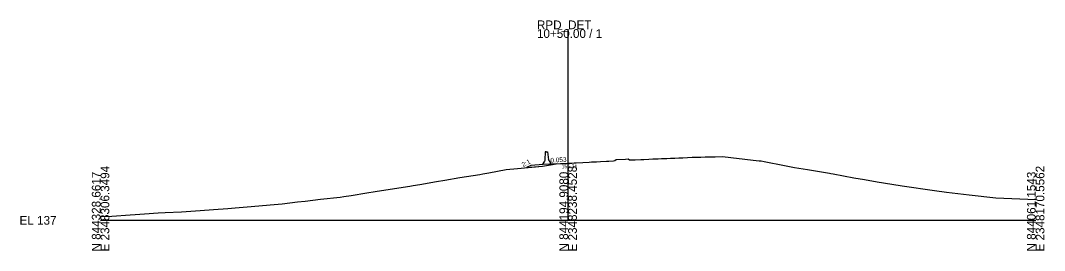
# Model space of a CAD drawing. Extents: x -26 to 2348503, y -10 to 844218.
# Drawn here: x -25.7 to 302.8, y 490.3 to 564.1 of the extents above; entities that cross this region are included whole.
import ezdxf

# ---------------------------------------------------------------- set-up
doc = ezdxf.new("R2010")
doc.units = 0
for name, color, linetype in [('Default', 7, 'Continuous'), ('Exist Cross Section Cell', 7, 'Continuous'), ('Exist XS Center Line Elevation Label', 7, 'Continuous'), ('Exist XS Ground Line', 7, 'Continuous'), ('Old_Level_1', 7, 'Continuous'), ('Prop CMT Pvmt Surface', 7, 'Continuous'), ('Prop CMT Slope Grass', 7, 'Continuous'), ('Prop XS Earthwork Shape', 7, 'Continuous'), ('Prop XS SE Text', 7, 'Continuous'), ('Typical Median Barrier CELL', 7, 'Continuous')]:
    doc.layers.add(name, color=color, linetype=linetype)

# ---------------------------------------------------------------- blocks, each defined once
blk = doc.blocks.new('TYPE T DOUBLE FACE BARRIER')
at = {"layer": 'Typical Median Barrier CELL'}
for p, q in [((-0.33, 3.83), (-0.6, 1.3)), ((0, 3.83), (-0.33, 3.83)), ((0, 3.83), (0.33, 3.83)), ((0.33, 3.83), (0.6, 1.3)), ((-0.75, 0.91), (-1.21, 0.25)), ((-1.21, -0.17), (-1.21, 0.25)), ((0, 0), (0, 0)), ((0.75, 0.91), (1.21, 0.25)), ((1.21, -0.17), (1.21, 0.25)), ((-1.21, -0.17), (1.21, -0.17))]:
    blk.add_line(p, q, dxfattribs=at)
for centre, start, end in [((-1.43, 1.38), 325.0039, 353.9447), ((1.43, 1.38), 186.0553, 214.9937)]:
    blk.add_arc(centre, 0.833, start, end, dxfattribs=at)

msp = doc.modelspace()

# ---------------------------------------------------------------- linework, layer by layer
at = {"layer": 'Exist Cross Section Cell'}
for p, q in [((150, 500), (150, 561.34)), ((0, 500), (150, 500)), ((150, 500), (300, 500))]:
    msp.add_line(p, q, dxfattribs=at)
at = {"layer": 'Exist XS Ground Line'}
msp.add_lwpolyline([(0, 501.22), (3.64, 501.37), (9.54, 501.81), (11.08, 501.89), (14.11, 502.12), (18.52, 502.39), (20.76, 502.52), (25.96, 502.71), (31.97, 503.18), (36.2, 503.5), (40.83, 503.82), (43.19, 504.01), (48.27, 504.43), (54.4, 504.92), (55.71, 505.05), (58.29, 505.32), (63.15, 505.94), (65.62, 506.19), (70.59, 506.77), (76.83, 507.48), (78.03, 507.6), (80.38, 507.97), (85.47, 508.79), (88.05, 509.24), (92.91, 510.03), (99.26, 510.97), (100.34, 511.15), (102.48, 511.52), (107.78, 512.44), (110.48, 512.9), (115.22, 513.7), (121.69, 514.76), (122.66, 514.94), (124.57, 515.26), (130.1, 516.26), (133.75, 516.63), (141.73, 517.43), (145.03, 517.97), (146.18, 518.12), (147.57, 518.2), (148.2, 518.23), (149.2, 518.27), (150, 518.31), (151.24, 518.37), (151.94, 518.41), (152.61, 518.45), (154.71, 518.57), (156.79, 518.69), (157.52, 518.73), (159.12, 518.81), (160.34, 518.87), (162.27, 518.98), (163.08, 519.03), (164.51, 519.11), (165.02, 519.16), (165.4, 519.55), (168.44, 519.65), (169.3, 519.69), (169.7, 519.38), (170.14, 519.39), (170.5, 519.4), (171.56, 519.44), (173.31, 519.52), (173.97, 519.55), (174.31, 519.57), (175.85, 519.65), (177.15, 519.71), (177.74, 519.74), (178.86, 519.78), (179.97, 519.82), (181.1, 519.86), (181.68, 519.88), (182.9, 519.92), (184.27, 519.98), (185.52, 520.04), (186.84, 520.09), (188.33, 520.16), (189.82, 520.22), (190.68, 520.25), (191.1, 520.27), (192.53, 520.32), (193.92, 520.38), (194.41, 520.4), (195.03, 520.41), (196.05, 520.41), (197.15, 520.42), (199.49, 520.45), (209.39, 519.33), (211.24, 519.13), (211.93, 519.05), (212.94, 518.85), (219.37, 517.59), (222.63, 517), (226.8, 516.29), (233.84, 515.11), (234.24, 515.04), (235.04, 514.9), (241.68, 513.68), (245.06, 513.08), (249.12, 512.36), (256.56, 511.17), (257.13, 511.08), (267.49, 509.54), (271.44, 509.06), (278.65, 508.15), (287.23, 507.18), (300, 506.71)], dxfattribs=at)
at = {"layer": 'Prop CMT Pvmt Surface'}
msp.add_line((146.18, 518.12), (142, 517.9), dxfattribs=at)
at = {"layer": 'Prop CMT Slope Grass'}
for p, q in [((138, 517.58), (136.69, 516.92)), ((142, 517.9), (138, 517.58))]:
    msp.add_line(p, q, dxfattribs=at)
at = {"layer": 'Prop XS Earthwork Shape'}
msp.add_lwpolyline([(146.18, 518.12), (142, 517.9), (138, 517.58), (136.69, 516.92), (141.73, 517.43), (145.03, 517.97)], close=True, dxfattribs=at)

# ---------------------------------------------------------------- block references
at = {"layer": 'Old_Level_1', "yscale": -0.9999999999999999, "rotation": -177.10656027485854}
msp.add_blockref('TYPE T DOUBLE FACE BARRIER', (143.2, 518.13), dxfattribs=at)

# ---------------------------------------------------------------- texts
at = {"layer": 'Default'}
msp.add_text('-', height=0.0001, dxfattribs=at).set_placement((0, 500))
at = {"layer": 'Exist Cross Section Cell'}
for s, p in [('RPD_DET', (140, 561.34)), ('10+50.00 / 1', (140, 558.54)), ('EL 137', (-26, 498.6))]:
    msp.add_text(s, height=2.8, dxfattribs=at).set_placement(p)
for s, p in [('E 2348306.3494', (2.8, 490)), ('E 2348238.4528', (152.8, 490)), ('E 2348170.5562', (302.8, 490)), ('N 844328.6617', (0, 490)), ('N 844194.9080', (150, 490)), ('N 844061.1543', (300, 490))]:
    msp.add_text(s, height=2.8, rotation=90, dxfattribs=at).set_placement(p)
at = {"layer": 'Exist XS Center Line Elevation Label'}
msp.add_text('155.31', height=1.2, dxfattribs=at).set_placement((147.89, 516.71))
at = {"layer": 'Prop XS SE Text'}
for s, rotation, p in [('2:1', 26.5651, (135.56, 517.07)), ('0.053', 3.03, (144.35, 518.52))]:
    msp.add_text(s, height=1.5, rotation=rotation, dxfattribs=at).set_placement(p)

doc.saveas('drawing.dxf')
